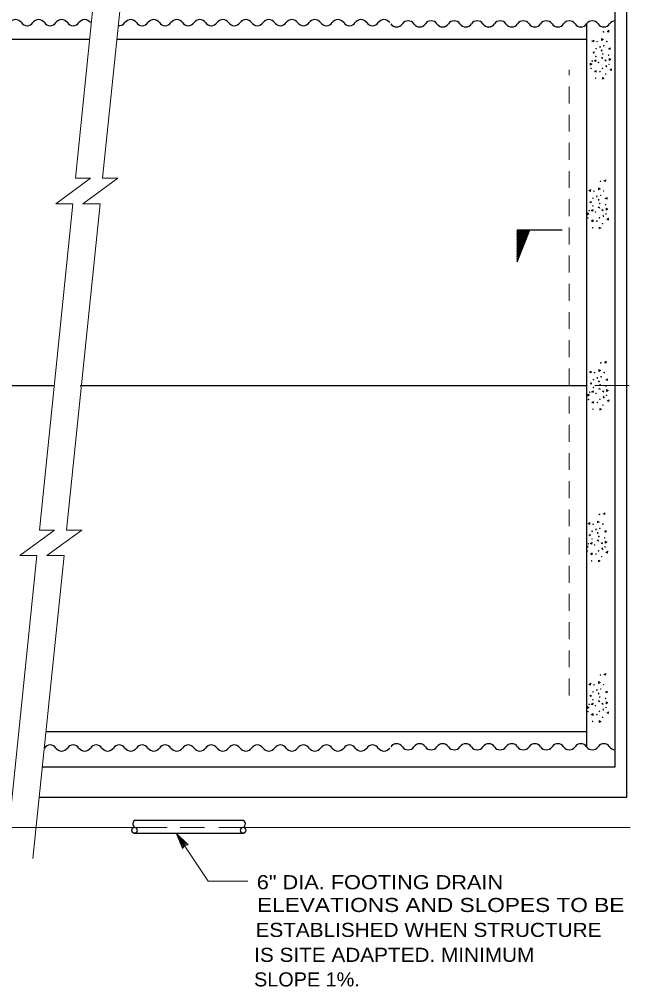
# Model space of a CAD drawing. Extents: x -24.3 to 17.7, y -17.6 to 12.4.
# Drawn here: x -10.43 to -5.03, y -0.59 to 7.99 of the extents above; entities that cross this region are included whole.
import ezdxf

# ---------------------------------------------------------------- set-up
doc = ezdxf.new("R2010")
doc.units = 0
doc.header["$LTSCALE"] = 0.05
doc.linetypes.add('MEDIUM_DASHED', pattern=[4.5, 3, -1.5])
doc.layers.add('1', color=7, linetype='Continuous', lineweight=13)
doc.layers.add('2', color=7, linetype='Continuous', lineweight=13)

msp = doc.modelspace()

# ---------------------------------------------------------------- linework, layer by layer
at = {"layer": '1'}
for p, q in [((-9.93669, 6.5824), (-9.68569, 9.0354)), ((-9.69669, 6.5824), (-9.44569, 9.0354)), ((-10.11069, 6.3554), (-9.80269, 6.5824)), ((-9.93669, 6.5824), (-9.80269, 6.5824)), ((-9.87069, 6.3554), (-9.56269, 6.5824)), ((-9.69669, 6.5824), (-9.56269, 6.5824)), ((-10.25569, 3.4634), (-9.95969, 6.3554)), ((-10.11069, 6.3554), (-9.95969, 6.3554)), ((-10.01569, 3.4634), (-9.71969, 6.3554)), ((-9.87069, 6.3554), (-9.71969, 6.3554)), ((-5.33469, 4.7464), (-5.03069, 4.7464)), ((-10.42969, 3.2364), (-10.12169, 3.4634)), ((-10.25569, 3.4634), (-10.12169, 3.4634)), ((-10.18969, 3.2364), (-9.88169, 3.4634)), ((-10.01569, 3.4634), (-9.88169, 3.4634)), ((-10.55369, 0.5514), (-10.27869, 3.2364)), ((-10.42969, 3.2364), (-10.27869, 3.2364)), ((-10.31369, 0.5514), (-10.03869, 3.2364)), ((-10.18969, 3.2364), (-10.03869, 3.2364)), ((-13.49969, 0.8254), (-9.12369, 0.8254)), ((-9.04369, 0.7754), (-8.76069, 0.3514)), ((-9.04369, 0.7754), (-8.93769, 0.6724)), ((-9.04369, 0.7754), (-8.98969, 0.6384)), ((-9.00869, 0.8254), (-8.79469, 0.8254)), ((-8.66569, 0.8254), (-5.02369, 0.8254)), ((-9.02269, 0.7444), (-8.95469, 0.6774)), ((-9.02269, 0.7444), (-8.98769, 0.6554)), ((-9.00269, 0.7144), (-8.98569, 0.6724)), ((-9.00269, 0.7144), (-8.96969, 0.6824)), ((-8.97569, 0.6744), (-8.98769, 0.6554)), ((-8.98069, 0.6804), (-8.98569, 0.6724)), ((-8.96969, 0.6824), (-8.98069, 0.6804)), ((-8.95469, 0.6774), (-8.97569, 0.6744)), ((-8.76069, 0.3514), (-8.40869, 0.3514))]:
    msp.add_line(p, q, dxfattribs=at)
at = {"layer": '1', "lineweight": 25}
for p, q in [((-5.05069, 1.0934), (-5.05069, 8.4474)), ((-5.15569, 1.3644), (-5.15569, 8.1284)), ((-5.40569, 1.5414), (-5.40569, 7.9564)), ((-18.37569, 7.8164), (-9.81169, 7.8164)), ((-9.57069, 7.8164), (-5.40769, 7.8164)), ((-18.37569, 4.7464), (-10.12369, 4.7464)), ((-9.89569, 4.7464), (-5.40469, 4.7464)), ((-10.19869, 1.6764), (-5.40769, 1.6764)), ((-10.23069, 1.3644), (-5.15569, 1.3644)), ((-10.25869, 1.0934), (-5.05069, 1.0934)), ((-9.41169, 0.8904), (-8.44869, 0.8904)), ((-9.41569, 0.7754), (-8.44669, 0.7754))]:
    msp.add_line(p, q, dxfattribs=at)
at = {"layer": '1', "linetype": 'MEDIUM_DASHED'}
msp.add_line((-5.56169, 1.9964), (-5.56169, 7.5444), dxfattribs=at)
at = {"layer": '1'}
msp.add_lwpolyline([(-8.93769, 0.6724), (-8.97169, 0.6674), (-8.98969, 0.6384)], dxfattribs=at)
at = {"layer": '1', "lineweight": 25}
for centre, radius, start, end in [((-10.46769, 7.9279), 0.06157, 34.07719, 145.9228), ((-10.26369, 7.9279), 0.06157, 34.07719, 145.9228), ((-10.05969, 7.9279), 0.06157, 34.07719, 145.9228), ((-9.85569, 7.9279), 0.06157, 34.07719, 145.9228), ((-9.44769, 7.9279), 0.06157, 34.07719, 145.9228), ((-9.24369, 7.9279), 0.06157, 34.07719, 145.9228), ((-9.03969, 7.9279), 0.06157, 34.07719, 145.9228), ((-8.83569, 7.9279), 0.06157, 34.07719, 145.9228), ((-8.63169, 7.9279), 0.06157, 34.07719, 145.9228), ((-8.42769, 7.9279), 0.06157, 34.07719, 145.9228), ((-8.22369, 7.9279), 0.06157, 34.07719, 145.9228), ((-8.01969, 7.9279), 0.06157, 34.07719, 145.9228), ((-7.81569, 7.9279), 0.06157, 34.07719, 145.9228), ((-7.61169, 7.9279), 0.06157, 34.07719, 145.9228), ((-7.40769, 7.9279), 0.06157, 34.07719, 145.9228), ((-7.20369, 7.9279), 0.06157, 34.07719, 145.9228), ((-6.98969, 7.9169), 0.06157, 34.07719, 145.9228), ((-6.78569, 7.9169), 0.06157, 34.07719, 145.9228), ((-6.58169, 7.9169), 0.06157, 34.07719, 145.9228), ((-6.37769, 7.9169), 0.06157, 34.07719, 145.9228), ((-6.17369, 7.9169), 0.06157, 34.07719, 145.9228), ((-5.96969, 7.9169), 0.06157, 34.07719, 145.9228), ((-5.76569, 7.9169), 0.06157, 34.07719, 145.9228), ((-5.56169, 7.9169), 0.06157, 34.07719, 145.9228), ((-5.35769, 7.9169), 0.06157, 34.07719, 145.9228), ((-5.15369, 7.9169), 0.06157, 92.83879, 145.9228), ((-10.36569, 7.9969), 0.06157, 214.07719, 325.9228), ((-10.16169, 7.9969), 0.06157, 214.07719, 325.9228), ((-9.95769, 7.9969), 0.06157, 214.07719, 325.9228), ((-9.54969, 7.9969), 0.06157, 260.45087, 325.9228), ((-9.34569, 7.9969), 0.06157, 214.07719, 325.9228), ((-9.14169, 7.9969), 0.06157, 214.07719, 325.9228), ((-8.93769, 7.9969), 0.06157, 214.07719, 325.9228), ((-8.73369, 7.9969), 0.06157, 214.07719, 325.9228), ((-8.52969, 7.9969), 0.06157, 214.07719, 325.9228), ((-8.32569, 7.9969), 0.06157, 214.07719, 325.9228), ((-8.12169, 7.9969), 0.06157, 214.07719, 325.9228), ((-7.91769, 7.9969), 0.06157, 214.07719, 325.9228), ((-7.71369, 7.9969), 0.06157, 214.07719, 325.9228), ((-7.50969, 7.9969), 0.06157, 214.07719, 325.9228), ((-7.30569, 7.9969), 0.06157, 214.07719, 325.9228), ((-7.09169, 7.9859), 0.06157, 214.07719, 325.9228), ((-6.88769, 7.9859), 0.06157, 214.07719, 325.9228), ((-6.68369, 7.9859), 0.06157, 214.07719, 325.9228), ((-6.47969, 7.9859), 0.06157, 214.07719, 325.9228), ((-6.27569, 7.9859), 0.06157, 214.07719, 325.9228), ((-6.07169, 7.9859), 0.06157, 214.07719, 325.9228), ((-5.86769, 7.9859), 0.06157, 214.07719, 325.9228), ((-5.66369, 7.9859), 0.06157, 214.07719, 325.9228), ((-5.45969, 7.9859), 0.06157, 214.07719, 325.9228), ((-5.25569, 7.9859), 0.06157, 214.07719, 325.9228), ((-10.16169, 1.4959), 0.06157, 34.0772, 145.92281), ((-9.95769, 1.4959), 0.06157, 34.0772, 145.92281), ((-9.75369, 1.4959), 0.06157, 34.0772, 145.92281), ((-9.54969, 1.4959), 0.06157, 34.0772, 145.92281), ((-9.34569, 1.4959), 0.06157, 34.0772, 145.92281), ((-9.14169, 1.4959), 0.06157, 34.0772, 145.92281), ((-8.93769, 1.4959), 0.06157, 34.0772, 145.92281), ((-8.73369, 1.4959), 0.06157, 34.0772, 145.92281), ((-8.52969, 1.4959), 0.06157, 34.0772, 145.92281), ((-8.32569, 1.4959), 0.06157, 34.0772, 145.92281), ((-8.12169, 1.4959), 0.06157, 34.0772, 145.92281), ((-7.91769, 1.4959), 0.06157, 34.0772, 145.92281), ((-7.71369, 1.4959), 0.06157, 34.0772, 145.92281), ((-7.50969, 1.4959), 0.06157, 34.0772, 145.92281), ((-7.30569, 1.4959), 0.06157, 34.0772, 145.92281), ((-7.09169, 1.5069), 0.06157, 34.0772, 145.92281), ((-6.88769, 1.5069), 0.06157, 34.0772, 145.92281), ((-6.68369, 1.5069), 0.06157, 34.0772, 145.92281), ((-6.47969, 1.5069), 0.06157, 34.0772, 145.92281), ((-6.27569, 1.5069), 0.06157, 34.0772, 145.92281), ((-6.07169, 1.5069), 0.06157, 34.0772, 145.92281), ((-5.86769, 1.5069), 0.06157, 34.0772, 145.92281), ((-5.66369, 1.5069), 0.06157, 34.0772, 145.92281), ((-5.45969, 1.5069), 0.06157, 34.0772, 145.92281), ((-5.25569, 1.5069), 0.06157, 34.0772, 145.92281), ((-10.05969, 1.5649), 0.06157, 214.0772, 325.92281), ((-9.85569, 1.5649), 0.06157, 214.0772, 325.92281), ((-9.65169, 1.5649), 0.06157, 214.0772, 325.92281), ((-9.44769, 1.5649), 0.06157, 214.0772, 325.92281), ((-9.24369, 1.5649), 0.06157, 214.0772, 325.92281), ((-9.03969, 1.5649), 0.06157, 214.0772, 325.92281), ((-8.83569, 1.5649), 0.06157, 214.0772, 325.92281), ((-8.63169, 1.5649), 0.06157, 214.0772, 325.92281), ((-8.42769, 1.5649), 0.06157, 214.0772, 325.92281), ((-8.22369, 1.5649), 0.06157, 214.0772, 325.92281), ((-8.01969, 1.5649), 0.06157, 214.0772, 325.92281), ((-7.81569, 1.5649), 0.06157, 214.0772, 325.92281), ((-7.61169, 1.5649), 0.06157, 214.0772, 325.92281), ((-7.40769, 1.5649), 0.06157, 214.0772, 325.92281), ((-7.20369, 1.5649), 0.06157, 214.0772, 325.92281), ((-6.98969, 1.5759), 0.06157, 214.0772, 325.92281), ((-6.78569, 1.5759), 0.06157, 214.0772, 325.92281), ((-6.58169, 1.5759), 0.06157, 214.0772, 325.92281), ((-6.37769, 1.5759), 0.06157, 214.0772, 325.92281), ((-6.17369, 1.5759), 0.06157, 214.0772, 325.92281), ((-5.96969, 1.5759), 0.06157, 214.0772, 325.92281), ((-5.76569, 1.5759), 0.06157, 214.0772, 325.92281), ((-5.56169, 1.5759), 0.06157, 214.0772, 325.92281), ((-5.35769, 1.5759), 0.06157, 214.0772, 325.92281), ((-5.15369, 1.5759), 0.06157, 214.0772, 262.4674), ((-9.39062, 0.85868), 0.03807, 123.5916, 232.71318), ((-8.46975, 0.85868), 0.03807, 307.28682, 56.4084)]:
    msp.add_arc(centre, radius, start, end, dxfattribs=at)
for centre in [(-9.41419, 0.8014), (-8.45119, 0.8014)]:
    msp.add_ellipse(centre, major_axis=(-0.0005, 0.027), ratio=0.833928, dxfattribs=at)
at = {"layer": '2'}
for p, q in [((-5.34369, 7.6914), (-5.35169, 7.7004)), ((-5.37069, 6.3654), (-5.37869, 6.3744)), ((-5.36669, 4.7564), (-5.37469, 4.7654)), ((-5.37869, 3.4124), (-5.38669, 3.4214)), ((-5.37069, 1.9884), (-5.37869, 1.9974))]:
    msp.add_line(p, q, dxfattribs=at)
at = {"layer": '2', "lineweight": 25}
for p, q in [((-6.02269, 5.8654), (-5.91969, 6.1264)), ((-6.02269, 5.8904), (-5.92869, 6.1264)), ((-6.02269, 5.9074), (-5.93569, 6.1264)), ((-6.02269, 5.9344), (-5.94669, 6.1264)), ((-6.02269, 5.9604), (-5.95669, 6.1264)), ((-6.02269, 5.9904), (-5.96869, 6.1264)), ((-6.02269, 6.0114), (-5.97669, 6.1264)), ((-6.02269, 6.0354), (-5.98569, 6.1264)), ((-6.02269, 6.0564), (-5.99469, 6.1264)), ((-6.02269, 6.0784), (-6.00369, 6.1264)), ((-6.02269, 6.0934), (-6.00969, 6.1264)), ((-6.02269, 6.1134), (-6.01769, 6.1264)), ((-6.02269, 6.1264), (-5.62569, 6.1264))]:
    msp.add_line(p, q, dxfattribs=at)
at = {"layer": '2'}
for points in [[(-5.22769, 7.8864), (-5.21269, 7.8794), (-5.21069, 7.8944), (-5.22769, 7.8824)], [(-5.36069, 7.8004), (-5.34569, 7.7924), (-5.34369, 7.8084), (-5.36069, 7.7964)], [(-5.26269, 7.8134), (-5.27569, 7.8054), (-5.27569, 7.8224), (-5.25969, 7.8134)], [(-5.29169, 7.7414), (-5.29469, 7.7484), (-5.28669, 7.7524), (-5.29069, 7.7414)], [(-5.27269, 7.7104), (-5.27969, 7.7154), (-5.27269, 7.7224), (-5.27169, 7.7114)], [(-5.21569, 7.7314), (-5.20069, 7.7234), (-5.19969, 7.7384), (-5.21569, 7.7274)], [(-5.35269, 7.7004), (-5.34169, 7.7024), (-5.34169, 7.6914)], [(-5.19569, 7.6344), (-5.20869, 7.6264), (-5.20869, 7.6434), (-5.19269, 7.6344)], [(-5.36269, 7.5934), (-5.37569, 7.5854), (-5.37569, 7.6024), (-5.36069, 7.5934)], [(-5.34169, 7.6244), (-5.32669, 7.6174), (-5.32469, 7.6324), (-5.34169, 7.6204)], [(-5.23369, 7.5714), (-5.23869, 7.5784), (-5.23369, 7.5854), (-5.23069, 7.5674)], [(-5.20369, 7.5454), (-5.18869, 7.5384), (-5.18669, 7.5544), (-5.20369, 7.5424)], [(-5.33969, 7.5304), (-5.32469, 7.5234), (-5.32369, 7.5394), (-5.33969, 7.5274)], [(-5.25569, 7.4674), (-5.26869, 7.4604), (-5.26869, 7.4764), (-5.25369, 7.4674)], [(-5.25469, 6.5604), (-5.23969, 6.5534), (-5.23769, 6.5684), (-5.25469, 6.5564)], [(-5.38769, 6.4744), (-5.37269, 6.4664), (-5.37069, 6.4824), (-5.38769, 6.4704)], [(-5.28969, 6.4874), (-5.30269, 6.4794), (-5.30269, 6.4964), (-5.28669, 6.4874)], [(-5.37969, 6.3744), (-5.36869, 6.3764), (-5.36869, 6.3654)], [(-5.31869, 6.4154), (-5.32169, 6.4224), (-5.31369, 6.4264), (-5.31769, 6.4154)], [(-5.29969, 6.3844), (-5.30669, 6.3894), (-5.29969, 6.3964), (-5.29869, 6.3854)], [(-5.24269, 6.4054), (-5.22769, 6.3974), (-5.22669, 6.4124), (-5.24269, 6.4014)], [(-5.38969, 6.2674), (-5.40269, 6.2594), (-5.40269, 6.2764), (-5.38769, 6.2674)], [(-5.36869, 6.2984), (-5.35369, 6.2914), (-5.35169, 6.3064), (-5.36869, 6.2944)], [(-5.22269, 6.3084), (-5.23569, 6.3004), (-5.23569, 6.3174), (-5.21969, 6.3084)], [(-5.36669, 6.2044), (-5.35169, 6.1974), (-5.35069, 6.2134), (-5.36669, 6.2014)], [(-5.26069, 6.2454), (-5.26569, 6.2524), (-5.26069, 6.2594), (-5.25769, 6.2414)], [(-5.23069, 6.2194), (-5.21569, 6.2124), (-5.21369, 6.2284), (-5.23069, 6.2164)], [(-5.28269, 6.1414), (-5.29569, 6.1344), (-5.29569, 6.1504), (-5.28069, 6.1414)], [(-5.25069, 4.9514), (-5.23569, 4.9444), (-5.23369, 4.9594), (-5.25069, 4.9474)], [(-5.38369, 4.8654), (-5.36869, 4.8574), (-5.36669, 4.8734), (-5.38369, 4.8614)], [(-5.31469, 4.8064), (-5.31769, 4.8134), (-5.30969, 4.8174), (-5.31369, 4.8064)], [(-5.28569, 4.8784), (-5.29869, 4.8704), (-5.29869, 4.8874), (-5.28269, 4.8784)], [(-5.23869, 4.7964), (-5.22369, 4.7884), (-5.22269, 4.8034), (-5.23869, 4.7924)], [(-5.37569, 4.7654), (-5.36469, 4.7674), (-5.36469, 4.7564)], [(-5.29569, 4.7754), (-5.30269, 4.7804), (-5.29569, 4.7874), (-5.29469, 4.7764)], [(-5.38569, 4.6584), (-5.39869, 4.6504), (-5.39869, 4.6674), (-5.38369, 4.6584)], [(-5.36469, 4.6894), (-5.34969, 4.6824), (-5.34769, 4.6974), (-5.36469, 4.6854)], [(-5.25669, 4.6364), (-5.26169, 4.6434), (-5.25669, 4.6504), (-5.25369, 4.6324)], [(-5.21869, 4.6994), (-5.23169, 4.6914), (-5.23169, 4.7084), (-5.21569, 4.6994)], [(-5.36269, 4.5954), (-5.34769, 4.5884), (-5.34669, 4.6044), (-5.36269, 4.5924)], [(-5.22669, 4.6104), (-5.21169, 4.6034), (-5.20969, 4.6194), (-5.22669, 4.6074)], [(-5.27869, 4.5324), (-5.29169, 4.5254), (-5.29169, 4.5414), (-5.27669, 4.5324)], [(-5.26269, 3.6074), (-5.24769, 3.6004), (-5.24569, 3.6154), (-5.26269, 3.6034)], [(-5.39569, 3.5214), (-5.38069, 3.5134), (-5.37869, 3.5294), (-5.39569, 3.5174)], [(-5.29769, 3.5344), (-5.31069, 3.5264), (-5.31069, 3.5434), (-5.29469, 3.5344)], [(-5.32669, 3.4624), (-5.32969, 3.4694), (-5.32169, 3.4734), (-5.32569, 3.4624)], [(-5.30769, 3.4314), (-5.31469, 3.4364), (-5.30769, 3.4434), (-5.30669, 3.4324)], [(-5.25069, 3.4524), (-5.23569, 3.4444), (-5.23469, 3.4594), (-5.25069, 3.4484)], [(-5.38769, 3.4214), (-5.37669, 3.4234), (-5.37669, 3.4124)], [(-5.37669, 3.3454), (-5.36169, 3.3384), (-5.35969, 3.3534), (-5.37669, 3.3414)], [(-5.23069, 3.3554), (-5.24369, 3.3474), (-5.24369, 3.3644), (-5.22769, 3.3554)], [(-5.39769, 3.3144), (-5.41069, 3.3064), (-5.41069, 3.3234), (-5.39569, 3.3144)], [(-5.37469, 3.2514), (-5.35969, 3.2444), (-5.35869, 3.2604), (-5.37469, 3.2484)], [(-5.26869, 3.2924), (-5.27369, 3.2994), (-5.26869, 3.3064), (-5.26569, 3.2884)], [(-5.23869, 3.2664), (-5.22369, 3.2594), (-5.22169, 3.2754), (-5.23869, 3.2634)], [(-5.29069, 3.1884), (-5.30369, 3.1814), (-5.30369, 3.1974), (-5.28869, 3.1884)], [(-5.25469, 2.1834), (-5.23969, 2.1764), (-5.23769, 2.1914), (-5.25469, 2.1794)], [(-5.38769, 2.0974), (-5.37269, 2.0894), (-5.37069, 2.1054), (-5.38769, 2.0934)], [(-5.28969, 2.1104), (-5.30269, 2.1024), (-5.30269, 2.1194), (-5.28669, 2.1104)], [(-5.37969, 1.9974), (-5.36869, 1.9994), (-5.36869, 1.9884)], [(-5.31869, 2.0384), (-5.32169, 2.0454), (-5.31369, 2.0494), (-5.31769, 2.0384)], [(-5.29969, 2.0074), (-5.30669, 2.0124), (-5.29969, 2.0194), (-5.29869, 2.0084)], [(-5.24269, 2.0284), (-5.22769, 2.0204), (-5.22669, 2.0354), (-5.24269, 2.0244)], [(-5.38969, 1.8904), (-5.40269, 1.8824), (-5.40269, 1.8994), (-5.38769, 1.8904)], [(-5.36869, 1.9214), (-5.35369, 1.9144), (-5.35169, 1.9294), (-5.36869, 1.9174)], [(-5.22269, 1.9314), (-5.23569, 1.9234), (-5.23569, 1.9404), (-5.21969, 1.9314)], [(-5.36669, 1.8274), (-5.35169, 1.8204), (-5.35069, 1.8364), (-5.36669, 1.8244)], [(-5.26069, 1.8684), (-5.26569, 1.8754), (-5.26069, 1.8824), (-5.25769, 1.8644)], [(-5.23069, 1.8424), (-5.21569, 1.8354), (-5.21369, 1.8514), (-5.23069, 1.8394)], [(-5.28269, 1.7644), (-5.29569, 1.7574), (-5.29569, 1.7734), (-5.28069, 1.7644)]]:
    msp.add_lwpolyline(points, dxfattribs=at)
for points in [[(-5.26569, 7.6434), (-5.27869, 7.6504), (-5.26969, 7.6544)], [(-5.23369, 7.6204), (-5.24569, 7.6284), (-5.23669, 7.6324)], [(-5.29269, 6.3174), (-5.30569, 6.3244), (-5.29669, 6.3284)], [(-5.26069, 6.2944), (-5.27269, 6.3024), (-5.26369, 6.3064)], [(-5.28869, 4.7084), (-5.30169, 4.7154), (-5.29269, 4.7194)], [(-5.25669, 4.6854), (-5.26869, 4.6934), (-5.25969, 4.6974)], [(-5.30069, 3.3644), (-5.31369, 3.3714), (-5.30469, 3.3754)], [(-5.26869, 3.3414), (-5.28069, 3.3494), (-5.27169, 3.3534)], [(-5.29269, 1.9404), (-5.30569, 1.9474), (-5.29669, 1.9514)], [(-5.26069, 1.9174), (-5.27269, 1.9254), (-5.26369, 1.9294)]]:
    msp.add_lwpolyline(points, close=True, dxfattribs=at)
at = {"layer": '2', "lineweight": 25}
msp.add_lwpolyline([(-6.02269, 6.1264), (-6.02269, 5.8424), (-5.91069, 6.1264)], dxfattribs=at)
at = {"layer": '2'}
for centre in [(-5.25913, 7.88115), (-5.32437, 7.7319), (-5.31575, 7.79377), (-5.2565, 7.7574), (-5.22987, 7.79527), (-5.32587, 7.66252), (-5.26512, 7.6854), (-5.21338, 7.67415), (-5.36862, 7.55677), (-5.3585, 7.6209), (-5.303, 7.60965), (-5.26775, 7.5579), (-5.20962, 7.59315), (-5.3285, 7.4694), (-5.29062, 7.52902), (-5.24, 7.50615), (-5.28613, 6.55515), (-5.34275, 6.46777), (-5.2835, 6.4314), (-5.25687, 6.46927), (-5.35137, 6.4059), (-5.29212, 6.3594), (-5.24038, 6.34815), (-5.3855, 6.2949), (-5.35288, 6.33652), (-5.33, 6.28365), (-5.23663, 6.26715), (-5.39562, 6.23077), (-5.31762, 6.20302), (-5.29475, 6.2319), (-5.267, 6.18015), (-5.3555, 6.1434), (-5.28212, 4.94615), (-5.33875, 4.85877), (-5.2795, 4.8224), (-5.25287, 4.86027), (-5.34887, 4.72752), (-5.34737, 4.7969), (-5.28812, 4.7504), (-5.23637, 4.73915), (-5.3815, 4.6859), (-5.326, 4.67465), (-5.23262, 4.65815), (-5.39162, 4.62177), (-5.31363, 4.59402), (-5.29075, 4.6229), (-5.263, 4.57115), (-5.3515, 4.5344), (-5.29413, 3.60215), (-5.35075, 3.51477), (-5.26487, 3.51627), (-5.35938, 3.4529), (-5.2915, 3.4784), (-5.36088, 3.38352), (-5.30012, 3.4064), (-5.24838, 3.39515), (-5.40362, 3.27777), (-5.3935, 3.3419), (-5.338, 3.33065), (-5.30275, 3.2789), (-5.24463, 3.31415), (-5.3635, 3.1904), (-5.32562, 3.25002), (-5.275, 3.22715), (-5.28613, 2.17815), (-5.34275, 2.09077), (-5.25687, 2.09227), (-5.35137, 2.0289), (-5.29212, 1.9824), (-5.2835, 2.0544), (-5.24038, 1.97115), (-5.3855, 1.9179), (-5.35288, 1.95952), (-5.33, 1.90665), (-5.23663, 1.89015), (-5.39562, 1.85377), (-5.31762, 1.82602), (-5.29475, 1.8549), (-5.267, 1.80315), (-5.3555, 1.7664)]:
    msp.add_circle(centre, 0.00244, dxfattribs=at)

# ---------------------------------------------------------------- texts
at = {"layer": '1'}
for s, width, p in [('6" DIA. FOOTING DRAIN', 1.15, (-8.33069, 0.2784)), ('ELEVATIONS AND SLOPES TO BE', 1.2, (-8.32869, 0.0764)), ('ESTABLISHED WHEN STRUCTURE', 1.1, (-8.34169, -0.1446)), ('IS SITE ADAPTED. MINIMUM', 1.1, (-8.35369, -0.3656)), ('SLOPE 1%.', 1.05, (-8.35469, -0.5836))]:
    msp.add_text(s, height=0.125, dxfattribs=dict(at, width=width)).set_placement(p)

doc.saveas('drawing.dxf')
